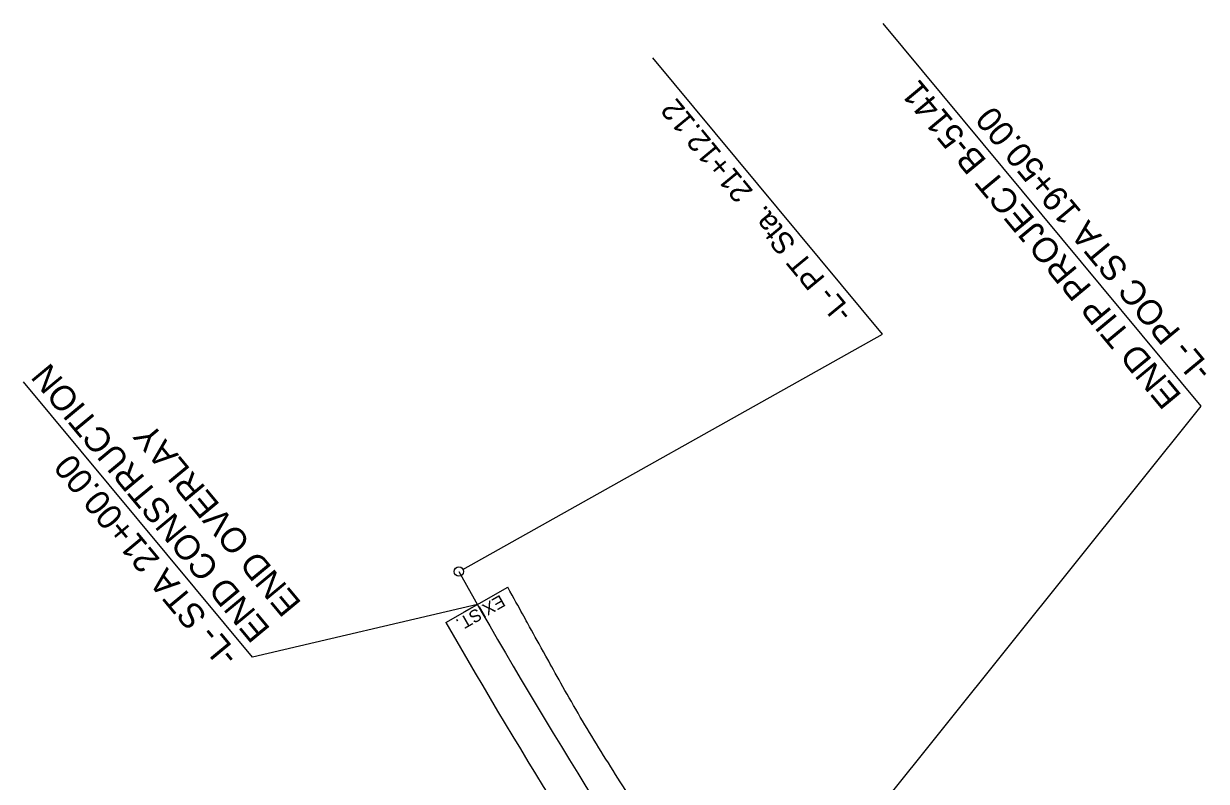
# Model space of a CAD drawing. Extents: x 2597570 to 2598622, y 852675 to 853890.
# Drawn here: x 2597569.6 to 2597949.6, y 853645.9 to 853889.5 of the extents above; entities that cross this region are included whole.
import ezdxf

# ---------------------------------------------------------------- set-up
doc = ezdxf.new("R2010")
doc.units = 0
for name, color, linetype in [('Exist Drainage Structure Bridge Pier Bent Interior', 7, 'Continuous'), ('Exist Hydrographic Channel Edge', 7, 'Continuous'), ('Exist Plan Preparation Drainage Arrows Symbol CELL', 7, 'Continuous'), ('Prop Drainage Structure Pipe Alternate 15in Label', 7, 'Continuous'), ('Prop Drainage Structure Pipe RCP 15in Class IV Label', 7, 'Continuous'), ('Prop Drainage Structure Plot Symbol 20 Scale', 7, 'Continuous'), ('Prop Earthen Structure Ditch Flow Line', 7, 'Continuous')]:
    doc.layers.add(name, color=color, linetype=linetype)

msp = doc.modelspace()

# ---------------------------------------------------------------- linework, layer by layer
at = {"layer": 'Exist Drainage Structure Bridge Pier Bent Interior'}
for p, q in [((2597845.5, 853789.67), (2597771.74, 853878.5)), ((2597710.74, 853714.1), (2597845.5, 853789.67))]:
    msp.add_line(p, q, dxfattribs=at)
msp.add_circle((2597709.43, 853713.37), 1.5, dxfattribs=at)
at = {"layer": 'Exist Hydrographic Channel Edge'}
msp.add_arc((2599247.12, 854575.63), 1762.95, 209.28143, 219.70669, dxfattribs=at)
msp.add_arc((2599247.12, 854575.63), 1762.95, 209.28143, 219.70669, dxfattribs=at)
at = {"layer": 'Exist Plan Preparation Drainage Arrows Symbol CELL'}
msp.add_line((2597715.4, 853702.82), (2597711.05, 853700.34), dxfattribs=at)
at = {"layer": 'Prop Drainage Structure Pipe RCP 15in Class IV Label'}
for p, q in [((2597947.9, 853766.55), (2597845.76, 853889.55)), ((2597643.1, 853685.9), (2597569.6, 853774.41)), ((2597795.11, 853575.8), (2597947.9, 853766.55)), ((2597715.4, 853702.82), (2597643.1, 853685.9))]:
    msp.add_line(p, q, dxfattribs=at)
at = {"layer": 'Prop Drainage Structure Plot Symbol 20 Scale'}
msp.add_line((2597705.28, 853697.05), (2597725.12, 853708.35), dxfattribs=at)
msp.add_arc((2599247.12, 854575.63), 1774.6, 209.67537, 214.55037, dxfattribs=at)
msp.add_open_spline([(2597803.86, 853581.83), (2597798.56, 853589.34), (2597793.37, 853596.93), (2597788.17, 853604.52), (2597782.96, 853612.1), (2597777.92, 853619.79), (2597772.94, 853627.54), (2597760.49, 853646.95), (2597748.27, 853666.52), (2597737.11, 853686.69), (2597733.11, 853693.91), (2597729.11, 853701.13), (2597725.12, 853708.35)], degree=3, dxfattribs=at)

# ---------------------------------------------------------------- texts
at = {"layer": 'Exist Drainage Structure Bridge Pier Bent Interior'}
msp.add_text('-L- PT Sta.  21+12.12 ', height=7, rotation=129.5051, dxfattribs=at).set_placement((2597836.31, 853796.76))
at = {"layer": 'Prop Drainage Structure Pipe Alternate 15in Label'}
for s, rotation, p in [('END TIP PROJECT B-5141', 129.7066, (2597941.9, 853769.99)), ('-L- POC STA 19+50.00', 129.7066, (2597951.9, 853778.29)), ('END CONSTRUCTION', 129.7067, (2597649.11, 853694.95)), ('END OVERLAY', 129.7067, (2597659.11, 853703.26)), ('-L- STA 21+00.00', 129.7067, (2597639.11, 853686.65))]:
    msp.add_text(s, height=8, rotation=rotation, dxfattribs=at).set_placement(p)
at = {"layer": 'Prop Earthen Structure Ditch Flow Line'}
msp.add_text('EXIST.', height=4, rotation=209.6878, dxfattribs=at).set_placement((2597722.77, 853706.06))

doc.saveas('drawing.dxf')
